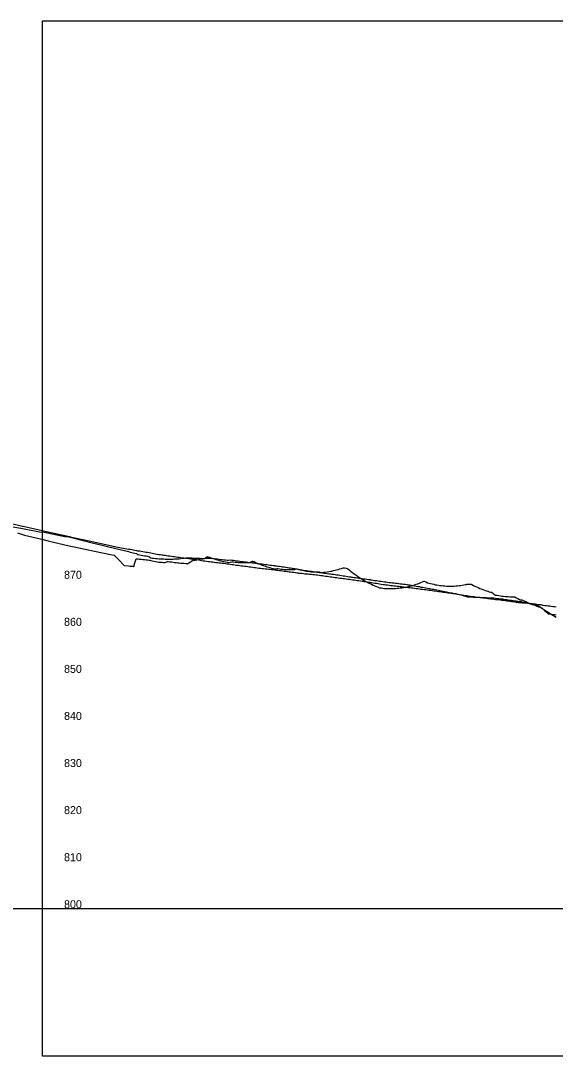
# Model space of a CAD drawing. Extents: x 1459978 to 1464152, y 1125650 to 1128602.
# Drawn here: x 1461053 to 1461621, y 1127502 to 1128602 of the extents above; entities that cross this region are included whole.
import ezdxf

# ---------------------------------------------------------------- set-up
doc = ezdxf.new("R2010")
doc.units = 0
for name, color, linetype in [('BR_EXIST_GROUND_LT', 7, 'Continuous'), ('BR_EXIST_GROUND_RT', 7, 'Continuous'), ('RD_DDB_ElevTX', 7, 'Continuous'), ('RD_DDB_Profile_EX', 7, 'Continuous'), ('RD_GPK_Profile_Cell', 7, 'Continuous'), ('RD_SHT_ShtClip', 7, 'Continuous')]:
    doc.layers.add(name, color=color, linetype=linetype)

msp = doc.modelspace()

# ---------------------------------------------------------------- linework, layer by layer
at = {"layer": 'BR_EXIST_GROUND_LT'}
msp.add_lwpolyline([(1461049.3, 1128058.1), (1461056.8, 1128055.8), (1461075, 1128051.3), (1461081.7, 1128049.8), (1461100.9, 1128045), (1461105.9, 1128043.9), (1461111.4, 1128042.8), (1461130.9, 1128038.7), (1461148.2, 1128035.2), (1461152, 1128034.4), (1461156.5, 1128029.8), (1461162.5, 1128023.4), (1461167.2, 1128023), (1461168.9, 1128022.9), (1461170.6, 1128022.7), (1461172.3, 1128022.6), (1461172.9, 1128022.5), (1461174, 1128026.3), (1461175.2, 1128030.7), (1461175.6, 1128030.7), (1461177.3, 1128030.5), (1461179, 1128030.3), (1461180.7, 1128030.2), (1461182.4, 1128030), (1461184.1, 1128029.8), (1461185.8, 1128029.6), (1461187.5, 1128029.4), (1461189.2, 1128029.2), (1461190, 1128029.1), (1461190.8, 1128028.9), (1461192.5, 1128028.5), (1461194.2, 1128028.2), (1461195.9, 1128027.8), (1461197.6, 1128027.4), (1461199.3, 1128027.1), (1461201, 1128027), (1461202.7, 1128026.9), (1461204.4, 1128026.7), (1461206.2, 1128026.6), (1461207.7, 1128027.4), (1461208.7, 1128027.7), (1461209.4, 1128027.6), (1461211.1, 1128027.4), (1461212.8, 1128027.2), (1461214.5, 1128027), (1461216.2, 1128026.8), (1461217.9, 1128026.6), (1461219.6, 1128026.4), (1461221.2, 1128026.2), (1461222.9, 1128026.1), (1461224.6, 1128025.9), (1461226.3, 1128025.8), (1461228, 1128025.6), (1461229.7, 1128025.5), (1461230.4, 1128025.4), (1461231.4, 1128026.2), (1461233.1, 1128027.4), (1461234.8, 1128028.6), (1461235.3, 1128029), (1461236.4, 1128029.1), (1461238.1, 1128029.3), (1461239.8, 1128029.6), (1461241.5, 1128029.8), (1461243.2, 1128030.1), (1461244.9, 1128030.4), (1461246.6, 1128030.7), (1461248.5, 1128031.1), (1461250, 1128032.3), (1461251, 1128033.1), (1461251.6, 1128032.8), (1461253.3, 1128032.2), (1461255, 1128031.6), (1461256.7, 1128031), (1461258.4, 1128030.4), (1461260.1, 1128029.9), (1461261.8, 1128029.4), (1461263.5, 1128028.9), (1461265.2, 1128028.5), (1461266.8, 1128028), (1461268.5, 1128027.6), (1461270.2, 1128027.3), (1461271.9, 1128026.9), (1461273, 1128026.7), (1461273.6, 1128026.8), (1461275.3, 1128027.1), (1461277, 1128027.4), (1461277.3, 1128027.5), (1461278.7, 1128027.3), (1461280.4, 1128027.1), (1461282, 1128026.9), (1461283.7, 1128026.8), (1461285.4, 1128026.7), (1461287.1, 1128026.6), (1461288.8, 1128026.6), (1461290.5, 1128026.6), (1461292.2, 1128026.6), (1461293.9, 1128026.7), (1461295.8, 1128026.8), (1461297.2, 1128027.3), (1461298.9, 1128028), (1461299.4, 1128028.2), (1461300.6, 1128027.6), (1461302.3, 1128026.8), (1461304, 1128026), (1461305.7, 1128025.3), (1461307.4, 1128024.6), (1461309.1, 1128024), (1461310.8, 1128023.4), (1461312.4, 1128022.8), (1461314.1, 1128022.2), (1461315.8, 1128021.7), (1461317.5, 1128021.3), (1461319.2, 1128020.8), (1461320.9, 1128020.4), (1461322.6, 1128020.1), (1461323.4, 1128019.9), (1461324.3, 1128020), (1461325.6, 1128020.2), (1461326, 1128020.2), (1461327.6, 1128019.9), (1461329.3, 1128019.7), (1461331, 1128019.5), (1461332.7, 1128019.4), (1461334.4, 1128019.3), (1461336.1, 1128019.2), (1461337.8, 1128019.2), (1461339.5, 1128019.2), (1461341.2, 1128019.2), (1461342.8, 1128019.3), (1461343.9, 1128019.4), (1461344.5, 1128019.7), (1461345.4, 1128020), (1461346.2, 1128019.8), (1461347.9, 1128019.3), (1461349.6, 1128018.9), (1461351.3, 1128018.5), (1461353, 1128018.1), (1461354.7, 1128017.8), (1461356.4, 1128017.5), (1461358, 1128017.3), (1461359.7, 1128017.1), (1461361.4, 1128016.9), (1461363.1, 1128016.8), (1461364.8, 1128016.7), (1461366.5, 1128016.7), (1461368.2, 1128016.7), (1461369.9, 1128016.7), (1461371.8, 1128016.1), (1461373.2, 1128016.2), (1461374.9, 1128016.3), (1461376.6, 1128016.5), (1461378.3, 1128016.7), (1461380, 1128017), (1461381.7, 1128017.3), (1461383.4, 1128017.6), (1461385.1, 1128018), (1461386.8, 1128018.4), (1461388.4, 1128018.8), (1461390.1, 1128019.3), (1461391.8, 1128019.8), (1461393.5, 1128020.4), (1461395.4, 1128021.1), (1461396.9, 1128021.1), (1461398.6, 1128020.6), (1461399.7, 1128020.3), (1461400.3, 1128019.9), (1461402, 1128018.5), (1461403.6, 1128017.2), (1461405.3, 1128015.9), (1461407, 1128014.6), (1461408.7, 1128013.4), (1461410.4, 1128012.3), (1461412.1, 1128011.1), (1461413.8, 1128010), (1461415.5, 1128009), (1461417.2, 1128008), (1461418.8, 1128007), (1461420.5, 1128006), (1461422.2, 1128005.1), (1461423.6, 1128004.5), (1461423.9, 1128004.3), (1461425.6, 1128003.5), (1461427.3, 1128002.7), (1461429, 1128001.9), (1461430.7, 1128001.2), (1461432.4, 1128000.5), (1461434, 1127999.9), (1461434.4, 1127999.8), (1461435.7, 1127999.6), (1461437.4, 1127999.4), (1461439.1, 1127999.2), (1461440.8, 1127999.1), (1461442.5, 1127999), (1461444.2, 1127999), (1461445.9, 1127999), (1461447.6, 1127999), (1461449.2, 1127999), (1461450.9, 1127999.1), (1461452.6, 1127999.3), (1461454.3, 1127999.5), (1461456, 1127999.7), (1461457.7, 1127999.9), (1461459.4, 1128000.2), (1461460, 1128000.3), (1461461.3, 1128000.3), (1461462.8, 1128000.6), (1461464.4, 1128001), (1461466.1, 1128001.4), (1461467.8, 1128001.9), (1461469.5, 1128002.4), (1461471.2, 1128002.9), (1461472.9, 1128003.5), (1461474.6, 1128004.1), (1461476.3, 1128004.7), (1461478, 1128005.4), (1461479.6, 1128006.1), (1461480.9, 1128006.7), (1461481.4, 1128006.8), (1461483, 1128006), (1461484.8, 1128005.2), (1461486.4, 1128004.7), (1461488.1, 1128004.3), (1461489.8, 1128003.9), (1461491.5, 1128003.5), (1461493.2, 1128003.1), (1461494.8, 1128002.8), (1461496.5, 1128002.5), (1461498.2, 1128002.3), (1461499.9, 1128002.1), (1461501.6, 1128001.9), (1461503.3, 1128001.8), (1461505, 1128001.7), (1461506.7, 1128001.6), (1461507.8, 1128001.6), (1461508.4, 1128001.6), (1461510, 1128001.6), (1461511.7, 1128001.6), (1461513.4, 1128001.7), (1461515.1, 1128001.8), (1461516.8, 1128001.9), (1461518.5, 1128002.1), (1461520.2, 1128002.3), (1461521.9, 1128002.6), (1461523.6, 1128002.9), (1461525.2, 1128003.2), (1461526.5, 1128003.4), (1461526.9, 1128003.5), (1461528.6, 1128003.5), (1461530.3, 1128003.6), (1461531.2, 1128003.7), (1461532, 1128003.3), (1461533.7, 1128002.4), (1461535.4, 1128001.6), (1461537.1, 1128000.8), (1461538.8, 1128000), (1461540.4, 1127999.2), (1461542.1, 1127998.6), (1461543.8, 1127997.9), (1461545.5, 1127997.3), (1461547.2, 1127996.7), (1461548.9, 1127996.1), (1461550.6, 1127995.6), (1461552.3, 1127995.1), (1461552.9, 1127995), (1461554, 1127994.3), (1461555.6, 1127993.2), (1461557.3, 1127992.1), (1461559, 1127991.8), (1461560.7, 1127991.5), (1461562.4, 1127991.2), (1461564.1, 1127991), (1461565.8, 1127990.8), (1461567.5, 1127990.6), (1461569.2, 1127990.5), (1461570.8, 1127990.4), (1461572.5, 1127990.3), (1461574.2, 1127990.3), (1461575.9, 1127990.3), (1461577.7, 1127990.3), (1461579.3, 1127989.3), (1461581, 1127988.3), (1461582.7, 1127987.3), (1461583.2, 1127987), (1461584.4, 1127987), (1461585.2, 1127987.1), (1461586, 1127986.7), (1461587.7, 1127985.9), (1461589.4, 1127985.1), (1461591.1, 1127984.3), (1461592.8, 1127983.6), (1461594.5, 1127982.9), (1461596.2, 1127982.2), (1461597.9, 1127981.6), (1461599.6, 1127980.9), (1461601.2, 1127980.3), (1461602.9, 1127979.7), (1461604.6, 1127979.2), (1461606.5, 1127978.6), (1461608, 1127977.1), (1461609.7, 1127975.4), (1461611.4, 1127973.8), (1461613.1, 1127972.2), (1461614.8, 1127972), (1461616.4, 1127971.8), (1461618.1, 1127971.6), (1461619.8, 1127971.4), (1461621.5, 1127971.2)], dxfattribs=at)
at = {"layer": 'BR_EXIST_GROUND_RT'}
msp.add_lwpolyline([(1461044.4, 1128064.6), (1461052.7, 1128063.2), (1461072.7, 1128059.2), (1461077.6, 1128058.9), (1461099.7, 1128054.4), (1461102.5, 1128054.2), (1461105.2, 1128053.6), (1461106.8, 1128053.3), (1461130.1, 1128047.3), (1461131.7, 1128047), (1461153.7, 1128041.4), (1461167.2, 1128038.2), (1461168.9, 1128037.8), (1461170.6, 1128037.4), (1461172.3, 1128037), (1461174, 1128036.6), (1461175.6, 1128036.2), (1461176, 1128036), (1461176.8, 1128035.3), (1461177.3, 1128035.2), (1461179, 1128034.9), (1461180.7, 1128034.5), (1461182.4, 1128034.2), (1461184.1, 1128033.9), (1461185.8, 1128033.7), (1461187.5, 1128033.4), (1461188.7, 1128033.2), (1461189.2, 1128032.8), (1461190.9, 1128031.5), (1461192.5, 1128031.3), (1461194.2, 1128031.1), (1461195.9, 1128030.9), (1461197.6, 1128030.8), (1461199.3, 1128030.6), (1461201, 1128030.5), (1461202.7, 1128030.4), (1461204.4, 1128030.4), (1461206, 1128030.3), (1461207.7, 1128030.3), (1461209.4, 1128030.3), (1461211.2, 1128030.3), (1461212.1, 1128030.3), (1461212.8, 1128030.3), (1461214.5, 1128030.3), (1461216.2, 1128030.4), (1461217.9, 1128030.5), (1461219.6, 1128030.6), (1461221.2, 1128030.7), (1461222.9, 1128030.9), (1461224.6, 1128031.1), (1461226.3, 1128031.3), (1461228, 1128031.5), (1461229.6, 1128031.7), (1461231.4, 1128031.6), (1461233.1, 1128031.5), (1461234.1, 1128031.5), (1461234.8, 1128031.4), (1461236.4, 1128031.4), (1461236.9, 1128031.3), (1461238.1, 1128031.3), (1461239.8, 1128031.2), (1461241.5, 1128031.2), (1461243.2, 1128031.1), (1461244.9, 1128031), (1461246.6, 1128031), (1461247.4, 1128031), (1461248.3, 1128031), (1461250, 1128031.1), (1461251.6, 1128031.1), (1461253.3, 1128031.2), (1461254, 1128031.2), (1461255, 1128031.1), (1461256.7, 1128031), (1461257.1, 1128031), (1461258.4, 1128030.8), (1461260.1, 1128030.6), (1461261.8, 1128030.4), (1461263.5, 1128030.2), (1461265.2, 1128030), (1461266.8, 1128029.8), (1461268.5, 1128029.6), (1461270.2, 1128029.4), (1461271.9, 1128029.2), (1461273.1, 1128029.1), (1461273.6, 1128029.2), (1461275.4, 1128029.4), (1461277, 1128029.2), (1461278.7, 1128029), (1461280.4, 1128028.8), (1461282, 1128028.5), (1461283.7, 1128028.3), (1461285.4, 1128028.1), (1461287.1, 1128027.9), (1461288.8, 1128027.7), (1461290.5, 1128027.5), (1461292.2, 1128027.3), (1461293.9, 1128027), (1461295.6, 1128026.8), (1461297.2, 1128026.6), (1461298.2, 1128026.5), (1461298.5, 1128026.4), (1461298.9, 1128026.4), (1461300.6, 1128026.2), (1461302.3, 1128026), (1461304, 1128025.7), (1461305.7, 1128025.5), (1461307.4, 1128025.3), (1461309.1, 1128025.1), (1461310.8, 1128024.9), (1461312.4, 1128024.7), (1461314.1, 1128024.5), (1461315.8, 1128024.2), (1461317.4, 1128024), (1461319.2, 1128023.8), (1461320.9, 1128023.6), (1461321.9, 1128023.4), (1461322.2, 1128023.4), (1461322.6, 1128023.3), (1461324.3, 1128023.1), (1461326, 1128022.8), (1461327.6, 1128022.6), (1461329.3, 1128022.4), (1461331, 1128022.1), (1461332.7, 1128021.9), (1461334.4, 1128021.6), (1461336.1, 1128021.4), (1461337.8, 1128021.1), (1461339.5, 1128020.9), (1461341.2, 1128020.6), (1461342.8, 1128020.4), (1461343.7, 1128020.2), (1461344.5, 1128020.1), (1461346.2, 1128019.9), (1461347.9, 1128019.5), (1461349.6, 1128019.2), (1461350.9, 1128019), (1461351.3, 1128018.9), (1461353, 1128018.6), (1461354.7, 1128018.3), (1461356.4, 1128018.1), (1461358, 1128017.8), (1461359.7, 1128017.6), (1461361.7, 1128017.4), (1461363.1, 1128017.2), (1461364.8, 1128016.9), (1461366.5, 1128016.7), (1461368.2, 1128016.5), (1461369.9, 1128016.2), (1461371.6, 1128016), (1461373.2, 1128015.8), (1461374.9, 1128015.5), (1461376.6, 1128015.3), (1461378.3, 1128015), (1461380, 1128014.8), (1461381.8, 1128014.5), (1461383.4, 1128014.3), (1461384.7, 1128014.2), (1461385.1, 1128014.1), (1461386.8, 1128013.9), (1461388.4, 1128013.6), (1461390.1, 1128013.4), (1461391.8, 1128013.1), (1461393.5, 1128012.9), (1461395.2, 1128012.6), (1461396.9, 1128012.4), (1461398.6, 1128012.1), (1461400.4, 1128011.8), (1461402, 1128011.6), (1461403.6, 1128011.3), (1461404.3, 1128011.2), (1461405.3, 1128011), (1461407, 1128010.8), (1461408.7, 1128010.6), (1461410.4, 1128010.4), (1461412.1, 1128010.1), (1461413.8, 1128009.9), (1461415.5, 1128009.7), (1461417.2, 1128009.4), (1461418.8, 1128009.2), (1461420.5, 1128009), (1461422.2, 1128008.7), (1461423.9, 1128008.5), (1461424.3, 1128008.4), (1461425.6, 1128008.2), (1461427.3, 1128007.9), (1461429, 1128007.7), (1461430.7, 1128007.4), (1461432.4, 1128007.2), (1461434, 1128007), (1461435.7, 1128006.7), (1461437.4, 1128006.5), (1461439.1, 1128006.2), (1461440.8, 1128006), (1461442.5, 1128005.8), (1461444.2, 1128005.6), (1461445.9, 1128005.4), (1461447.6, 1128005.2), (1461449.2, 1128005), (1461450.9, 1128004.8), (1461452.6, 1128004.6), (1461454.3, 1128004.3), (1461456, 1128004.1), (1461457.7, 1128003.9), (1461459.4, 1128003.7), (1461461.1, 1128003.5), (1461462.8, 1128003.3), (1461463.4, 1128003.2), (1461464.4, 1128003.1), (1461465.7, 1128002.9), (1461466.1, 1128002.9), (1461467.8, 1128002.5), (1461469.5, 1128002.2), (1461471.2, 1128001.9), (1461472.9, 1128001.6), (1461474.6, 1128001.3), (1461476.3, 1128001), (1461478, 1128000.6), (1461479.6, 1128000.3), (1461481.3, 1128000), (1461483, 1127999.7), (1461484.7, 1127999.4), (1461486.4, 1127999.1), (1461486.8, 1127999.1), (1461487.1, 1127998.9), (1461488.1, 1127998.8), (1461490, 1127998.5), (1461491.5, 1127998.2), (1461493.2, 1127997.9), (1461494.8, 1127997.5), (1461496.5, 1127997.2), (1461498.2, 1127996.8), (1461499.9, 1127996.5), (1461501.6, 1127996.2), (1461503.3, 1127995.8), (1461505, 1127995.5), (1461506.7, 1127995.2), (1461508.4, 1127994.9), (1461510, 1127994.5), (1461511.2, 1127994.3), (1461511.7, 1127994.2), (1461513.4, 1127993.9), (1461515.1, 1127993.6), (1461516.8, 1127993.2), (1461517.4, 1127993.1), (1461518.5, 1127992.8), (1461520.2, 1127992.3), (1461521.9, 1127991.8), (1461523.6, 1127991.3), (1461525.2, 1127990.8), (1461527, 1127990.3), (1461528.6, 1127990.2), (1461530.3, 1127990.1), (1461532, 1127990.1), (1461533.7, 1127990), (1461535.4, 1127989.9), (1461537.1, 1127989.8), (1461538.8, 1127989.8), (1461539.2, 1127989.7), (1461540.4, 1127989.7), (1461542.1, 1127989.6), (1461543.8, 1127989.5), (1461545.5, 1127989.5), (1461547.2, 1127989.4), (1461548.9, 1127989.3), (1461550.6, 1127989.3), (1461552.3, 1127989.2), (1461554, 1127989.2), (1461554.7, 1127989.1), (1461555.6, 1127989), (1461557.3, 1127988.8), (1461559, 1127988.6), (1461560.7, 1127988.4), (1461562.4, 1127988.2), (1461564.1, 1127988), (1461564.7, 1127987.9), (1461565.8, 1127987.8), (1461567.5, 1127987.5), (1461569.2, 1127987.3), (1461570.8, 1127987), (1461572.5, 1127986.8), (1461574.2, 1127986.6), (1461575.9, 1127986.4), (1461577.6, 1127986.1), (1461579.3, 1127985.9), (1461581, 1127985.7), (1461583, 1127985.4), (1461584.4, 1127985.1), (1461586, 1127984.7), (1461587.7, 1127984.4), (1461589.4, 1127984), (1461591.1, 1127983.6), (1461592.8, 1127983.2), (1461594.5, 1127982.9), (1461596.2, 1127982.5), (1461597.9, 1127982.1), (1461599.6, 1127981.8), (1461601.2, 1127981.4), (1461602.5, 1127981.1), (1461602.9, 1127980.8), (1461604.6, 1127979.5), (1461605.4, 1127978.9), (1461606.3, 1127978.3), (1461606.9, 1127978), (1461608, 1127977.2), (1461609.7, 1127976.1), (1461611.4, 1127974.9), (1461613.1, 1127973.8), (1461614.8, 1127972.7), (1461616.4, 1127971.7), (1461618.1, 1127970.6), (1461619.8, 1127969.6), (1461621.5, 1127968.6)], dxfattribs=at)
at = {"layer": 'RD_DDB_Profile_EX'}
msp.add_lwpolyline([(1461031.3, 1128071.1), (1461054.6, 1128065.3), (1461055.2, 1128065.2), (1461079.9, 1128059.7), (1461104.6, 1128054.3), (1461105.1, 1128054.1), (1461105.1, 1128054.1), (1461130.2, 1128048.6), (1461154.1, 1128043.4), (1461167.2, 1128041), (1461168.9, 1128040.7), (1461170.6, 1128040.4), (1461172.3, 1128040.1), (1461174, 1128039.8), (1461175.6, 1128039.4), (1461176.8, 1128039.2), (1461177.3, 1128039.2), (1461179.1, 1128039), (1461180.7, 1128038.7), (1461182.4, 1128038.4), (1461184.1, 1128038.1), (1461185.8, 1128037.8), (1461187.5, 1128037.5), (1461189.2, 1128037.2), (1461190.8, 1128036.9), (1461192.5, 1128036.5), (1461194.2, 1128036.2), (1461195.9, 1128035.9), (1461197.6, 1128035.6), (1461199.3, 1128035.3), (1461201, 1128035), (1461201.3, 1128035), (1461202.7, 1128034.8), (1461203.3, 1128034.7), (1461204.4, 1128034.6), (1461205, 1128034.5), (1461206, 1128034.4), (1461207.7, 1128034.2), (1461209.4, 1128033.9), (1461211.1, 1128033.7), (1461212.8, 1128033.5), (1461214.5, 1128033.2), (1461216.2, 1128033), (1461217.9, 1128032.8), (1461219.6, 1128032.5), (1461221.2, 1128032.3), (1461222.9, 1128032.1), (1461224.6, 1128031.8), (1461226.3, 1128031.6), (1461228.2, 1128031.3), (1461229.7, 1128031.2), (1461230.5, 1128031.1), (1461231.4, 1128030.9), (1461233.1, 1128030.7), (1461234.8, 1128030.4), (1461236.4, 1128030.2), (1461238.1, 1128029.9), (1461239.8, 1128029.7), (1461241.5, 1128029.4), (1461243.2, 1128029.2), (1461244.9, 1128028.9), (1461246.6, 1128028.6), (1461248.3, 1128028.4), (1461250, 1128028.1), (1461251.9, 1128027.8), (1461252.8, 1128027.7), (1461253.3, 1128027.6), (1461255, 1128027.4), (1461256.7, 1128027.2), (1461258.4, 1128027), (1461260.1, 1128026.8), (1461261.8, 1128026.6), (1461263.5, 1128026.4), (1461265.2, 1128026.2), (1461266.8, 1128026), (1461268.5, 1128025.8), (1461270.2, 1128025.6), (1461271.9, 1128025.3), (1461273.6, 1128025.1), (1461275.3, 1128024.9), (1461277, 1128024.7), (1461278.7, 1128024.5), (1461280.4, 1128024.2), (1461282, 1128024), (1461283.7, 1128023.8), (1461285.4, 1128023.5), (1461287.1, 1128023.3), (1461288.8, 1128023.1), (1461290.5, 1128022.8), (1461292.2, 1128022.6), (1461293.9, 1128022.4), (1461295.6, 1128022.1), (1461297.2, 1128021.9), (1461298.9, 1128021.6), (1461300.9, 1128021.3), (1461301.5, 1128021.3), (1461302.3, 1128021.2), (1461304, 1128021), (1461305.7, 1128020.8), (1461307.4, 1128020.6), (1461309.1, 1128020.4), (1461310.8, 1128020.2), (1461312.4, 1128020), (1461314.1, 1128019.8), (1461315.8, 1128019.7), (1461317.5, 1128019.5), (1461319.2, 1128019.3), (1461320.9, 1128019.1), (1461322.6, 1128018.8), (1461324.3, 1128018.6), (1461326, 1128018.4), (1461327.6, 1128018.2), (1461329.3, 1128018), (1461331, 1128017.8), (1461332.7, 1128017.6), (1461334.4, 1128017.4), (1461336.1, 1128017.1), (1461337.8, 1128016.9), (1461339.5, 1128016.7), (1461341.2, 1128016.5), (1461342.8, 1128016.3), (1461344.5, 1128016), (1461346.2, 1128015.8), (1461346.9, 1128015.7), (1461347.3, 1128015.6), (1461347.9, 1128015.5), (1461349.6, 1128015.4), (1461351.3, 1128015.2), (1461353, 1128015), (1461354.7, 1128014.8), (1461356.4, 1128014.7), (1461358, 1128014.5), (1461359.7, 1128014.3), (1461361.4, 1128014.1), (1461363.1, 1128014), (1461364.8, 1128013.8), (1461366.5, 1128013.6), (1461368.2, 1128013.4), (1461369.9, 1128013.2), (1461371.5, 1128013), (1461372, 1128013), (1461373.2, 1128012.8), (1461374.9, 1128012.6), (1461376.6, 1128012.3), (1461378.3, 1128012.1), (1461380, 1128011.9), (1461381.7, 1128011.6), (1461383.4, 1128011.4), (1461385.1, 1128011.2), (1461386.8, 1128010.9), (1461388.4, 1128010.7), (1461390.1, 1128010.4), (1461391.8, 1128010.2), (1461393.5, 1128010), (1461395.2, 1128009.8), (1461396.9, 1128009.5), (1461398.6, 1128009.3), (1461400.3, 1128009.1), (1461402, 1128008.9), (1461403.6, 1128008.6), (1461405.3, 1128008.4), (1461407, 1128008.2), (1461408.7, 1128007.9), (1461410.4, 1128007.7), (1461412.1, 1128007.4), (1461413.8, 1128007.2), (1461415.5, 1128007), (1461417.2, 1128006.7), (1461417.7, 1128006.6), (1461418.8, 1128006.4), (1461420.5, 1128006.2), (1461422.2, 1128005.9), (1461422.7, 1128005.9), (1461423.9, 1128005.7), (1461425.6, 1128005.4), (1461427.3, 1128005.1), (1461429, 1128004.8), (1461430.7, 1128004.6), (1461432.4, 1128004.3), (1461434, 1128004), (1461435.7, 1128003.7), (1461437.8, 1128003.4), (1461438.3, 1128003.3), (1461439.1, 1128003.2), (1461440.8, 1128003), (1461442.5, 1128002.8), (1461444.2, 1128002.6), (1461445.9, 1128002.4), (1461447.6, 1128002.2), (1461449.2, 1128002), (1461450.9, 1128001.8), (1461452.6, 1128001.6), (1461454.3, 1128001.4), (1461456, 1128001.2), (1461457.7, 1128001), (1461459.4, 1128000.8), (1461461.1, 1128000.6), (1461462.8, 1128000.4), (1461464.4, 1128000.2), (1461464.8, 1128000.2), (1461466.1, 1128000), (1461467.8, 1127999.8), (1461469.5, 1127999.6), (1461471.2, 1127999.4), (1461472.9, 1127999.2), (1461474.6, 1127999), (1461476.3, 1127998.7), (1461478, 1127998.5), (1461479.6, 1127998.3), (1461481.3, 1127998.1), (1461483, 1127997.9), (1461484.7, 1127997.6), (1461486.4, 1127997.4), (1461486.8, 1127997.3), (1461488.1, 1127997.2), (1461489.8, 1127996.9), (1461491.5, 1127996.7), (1461493.2, 1127996.5), (1461494.8, 1127996.2), (1461496.5, 1127996), (1461498.2, 1127995.8), (1461499.9, 1127995.5), (1461501.6, 1127995.3), (1461503.3, 1127995), (1461505, 1127994.8), (1461506.7, 1127994.5), (1461508.4, 1127994.3), (1461510, 1127994), (1461511.7, 1127993.8), (1461513, 1127993.6), (1461513.4, 1127993.6), (1461515.1, 1127993.3), (1461516.8, 1127993), (1461518.5, 1127992.8), (1461520.2, 1127992.5), (1461521.9, 1127992.3), (1461523.6, 1127992), (1461525.2, 1127991.7), (1461526.9, 1127991.5), (1461528.6, 1127991.2), (1461530.3, 1127991), (1461532, 1127990.7), (1461533.7, 1127990.4), (1461534.3, 1127990.4), (1461535.4, 1127990.2), (1461537.1, 1127990), (1461538.8, 1127989.8), (1461540.4, 1127989.6), (1461542.1, 1127989.4), (1461543.8, 1127989.2), (1461545.5, 1127989), (1461547.2, 1127988.8), (1461548.9, 1127988.6), (1461550.6, 1127988.4), (1461552.3, 1127988.2), (1461554, 1127988), (1461555.6, 1127987.8), (1461557.3, 1127987.5), (1461559, 1127987.4), (1461560.1, 1127987.2), (1461560.7, 1127987.2), (1461562.4, 1127986.9), (1461564.1, 1127986.7), (1461565.8, 1127986.5), (1461567.5, 1127986.3), (1461569.2, 1127986), (1461570.8, 1127985.8), (1461572.5, 1127985.6), (1461574.2, 1127985.3), (1461575.9, 1127985.1), (1461577.6, 1127984.9), (1461579.3, 1127984.6), (1461581, 1127984.4), (1461581.7, 1127984.3), (1461582.7, 1127984.3), (1461583.5, 1127984.3), (1461584.4, 1127984.2), (1461586, 1127984), (1461587.7, 1127983.9), (1461589.4, 1127983.7), (1461591.1, 1127983.5), (1461592.8, 1127983.3), (1461594.5, 1127983.2), (1461596.2, 1127983), (1461597.9, 1127982.8), (1461599.6, 1127982.6), (1461601.2, 1127982.4), (1461602.9, 1127982.2), (1461604.6, 1127982), (1461605.5, 1127981.9), (1461606.3, 1127981.6), (1461607, 1127981.5), (1461608, 1127981.3), (1461609.7, 1127981.1), (1461610.7, 1127981), (1461611.4, 1127980.9), (1461613.1, 1127980.7), (1461614.8, 1127980.5), (1461616.4, 1127980.2), (1461618.1, 1127980), (1461619.8, 1127979.8), (1461621.5, 1127979.6)], dxfattribs=at)
at = {"layer": 'RD_GPK_Profile_Cell'}
msp.add_line((1460062.2, 1127659.1), (1464151.9, 1127659.1), dxfattribs=at)
at = {"layer": 'RD_SHT_ShtClip'}
msp.add_lwpolyline([(1461075.9, 1128602.2), (1462875.9, 1128602.2), (1462875.9, 1127502.2), (1461075.9, 1127502.2)], close=True, dxfattribs=at)

# ---------------------------------------------------------------- texts
at = {"layer": 'RD_DDB_ElevTX'}
for s, p in [('870', (1461098.7, 1128009.4)), ('860', (1461098.7, 1127959.4)), ('850', (1461098.7, 1127909.4)), ('840', (1461098.7, 1127859.4)), ('830', (1461098.7, 1127809.4)), ('820', (1461098.7, 1127759.4)), ('810', (1461098.7, 1127709.4)), ('800', (1461098.7, 1127659.4))]:
    msp.add_text(s, height=8.5, dxfattribs=at).set_placement(p)

doc.saveas('drawing.dxf')
